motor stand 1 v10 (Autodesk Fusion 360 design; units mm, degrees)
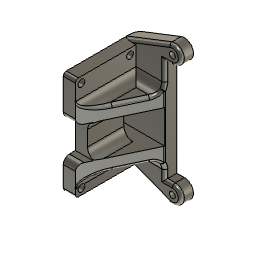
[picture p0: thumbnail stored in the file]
sketch "草图1" plane through (0, 0, 0) normal (1, 0, 0) x axis (0, 1, 0)
  line L1 (-10, -17) -> (10, -17)
  line L2 (10, -7.25) -> (10, 3.75)
  line L3 (10, 3.75) -> (6, 3.75)
  line L4 (-10, 3.75) -> (-6, -7.25)
  line L5 (-10, -7.25) -> (-10, 3.75)
  line L6 (-10, 17) -> (10, -17)
  line L7 (6, 3.75) -> (6, -7.25)
  line L8 (6, -7.25) -> (10, -7.25)
  line L9 (10, 0) -> (-10, 0)
  line L10 (10, -17) -> (10, 17)
  line L11 (-6, -7.25) -> (-10, -7.25)
  line L12 (-10, 17) -> (-10, -17)
  line L13 (10, 17) -> (-10, 17)
  line L14 (-6, 3.75) -> (-10, -7.25)
  line L15 (0, -17) -> (0, 17)
  line L16 (-10, 3.75) -> (-6, 3.75)
  line L17 (-6, 3.75) -> (-6, -7.25)
  line L18 (10, 17) -> (-10, -17)
  line L19 (10, -1.75) -> (-10, -1.75)
  circle C1 centre (-8, 15) radius 1.125
  circle C2 centre (-8, -15) radius 1.125
  circle C3 centre (8, 15) radius 1.125
  circle C4 centre (0, 8) radius 1.3
  circle C5 centre (0, 8) radius 4
  circle C6 centre (0, 8) radius 3
  circle C7 centre (8, -15) radius 1.125
  point P5 (0, 0)
  point P15 (0, 0)
  point P6 (-8, -1.75)
  point P8 (-10, -7.25)
  point P25 (0, 17)
  point P26 (0, -17)
  point P18 (10, -7.25)
  point P11 (6, -7.25)
  point P13 (-6, -7.25)
  point P9 (6, 3.75)
  point P24 (-6, 3.75)
  point P7 (-10, 3.75)
  point P14 (10, 3.75)
  point P4 (10, -1.75)
  point P20 (-10, -1.75)
  point P10 (0, 8)
  point P21 (-10, 0)
  point P29 (10, 0)
  point P16 (10, 17)
  point P17 (-10, 17)
  point P22 (10, -17)
  point P28 (-8, 15)
  horizontal L1
  perpendicular L1 L12
  parallel L1 L13
  parallel L10 L12
  coincident P5 L6
  coincident P5 L18
  coincident P5 P15
  horizontal L11
  perpendicular L11 L17
  parallel L11 L16
  parallel L5 L17
  coincident P6 L14
  coincident P6 L4
  coincident P8 L12
  coincident P6 L19
  midpoint P25 L13
  midpoint P26 L1
  symmetric P8 P18 L15
  symmetric P11 P13 L15
  symmetric P9 P24 L15
  symmetric P7 P14 L15
  midpoint P4 L2
  midpoint P20 L5
  coincident P10 L15
  midpoint P21 L12
  midpoint P29 L10
  symmetric C1 C3 L15
  symmetric C1 C2 L9
  symmetric C3 L9 C7
  concentric C4 C6
  concentric C5 C6
  dimension "d1" distance P16 P17 = 20
  dimension "d2" distance P16 P22 = 34
  dimension "d3" distance P13 P24 = 11
  dimension "d4" distance P7 P24 = 4
  dimension "d5" diameter C4 = 2.6
  dimension "d6" distance P28 L15 = 8
  dimension "d7" distance P28 L9 = 15
  dimension "d8" diameter C1 = 2.25
  dimension "d9" distance P10 P28 = 7
  dimension "d10" diameter C6 = 6
  dimension "d11" diameter C5 = 8
  dimension "d12" distance L1 L8 = 9.75 (= "10.25 mm - 0.5 mm")
extrude "拉伸1" new body sketch "草图1" profile of L1 C1 C2 L3 C3 L7 L8 L10 L11 L12 C7 L13 L16 L17 along normal blind 4
sketch "草图2" plane through (0, 10, 0) normal (0, 1, 0) x axis (-1, 0, 0)
  line L1 (0, 17) -> (0, 3.75)
  line L2 (-4, 17) -> (0, 17)
  line L3 (-4, 3.75) -> (-4, 17)
  line L4 (0, 3.75) -> (-4, 3.75)
  line L5 (0, 17) -> (-4, 17)
  line L6 (0, -17) -> (0, 17)
  line L7 (-4, -17) -> (0, -17)
  line L8 (-4, 17) -> (-4, -17)
  line L9 (-13.5, 17) -> (-4, 17)
  line L10 (-13.5, -17) -> (-13.5, 17)
  line L11 (-4, -17) -> (-13.5, -17)
  line L12 (-4, 17) -> (-4, -17)
  line L13 (0, 0) -> (-13.5, 0)
  line L14 (-14.9132, 22.7962) -> (0, 17)
  line L15 (-14.9132, -22.7962) -> (0, -17)
  line L16 (-16, 17) -> (-13.5, 17)
  line L17 (-16, -17) -> (-13.5, -17)
  line L18 (-2, -17) -> (-2, 17)
  line L19 (10.9132, 22.7962) -> (-4, 17)
  line L20 (9.5, 17) -> (0, 17)
  line L21 (9.5, -17) -> (9.5, 17)
  line L22 (12, 17) -> (9.5, 17)
  line L23 (0, -17) -> (9.5, -17)
  line L24 (12, -17) -> (9.5, -17)
  line L25 (10.9132, -22.7962) -> (-4, -17)
  circle C1 centre (-6, 0) radius 0.975
  circle C2 centre (-16, 20) radius 0.975
  circle C3 centre (-16, -20) radius 0.975
  circle C4 centre (-16, 20) radius 3
  circle C5 centre (-16, -20) radius 3
  circle C6 centre (12, 20) radius 3
  circle C7 centre (12, 20) radius 0.975
  circle C8 centre (12, -20) radius 3
  circle C9 centre (12, -20) radius 0.975
  point P4 (-4, 17)
  point P6 (-4, 17)
  point P13 (-13.5, 0)
  point P1 (0, 0)
  point P14 (0, 0)
  point P3 (0, 17)
  point P19 (0, 17)
  point P20 (-14.9132, 22.7962)
  point P21 (0, -17)
  point P22 (-14.9132, -22.7962)
  point P24 (-16, 17)
  point P25 (-16, -17)
  point P26 (-2, 17)
  point P27 (-2, -17)
  point P30 (0, 17)
  point P10 (-13.5, 17)
  point P31 (9.5, 17)
  point P11 (-13.5, -17)
  point P34 (9.5, -17)
  point P12 (-4, -17)
  point P36 (0, -17)
  point P28 (-4, 17)
  point P29 (10.9132, 22.7962)
  point P40 (-4, -17)
  point P41 (10.9132, -22.7962)
  point P35 (12, 17)
  point P37 (12, -17)
  point P7 (0, 17)
  point P8 (0, -17)
  point P16 (-16, 20)
  point P17 (-16, -20)
  point P15 (-6, 0)
  horizontal L5
  vertical L6
  horizontal L7
  vertical L8
  coincident P4 P6
  horizontal L9
  vertical L10
  horizontal L11
  vertical L12
  collinear L7 L11
  midpoint L10 P13
  coincident P1 P14
  equal C1 C2
  symmetric L13 C2 C3
  concentric C2 C4
  tangent L9 C4
  coincident P3 P19
  coincident C4 P20
  tangent C4 L14
  symmetric L13 C4 C5
  symmetric L13 P19 P21
  symmetric L13 P20 P22
  coincident C4 P24
  tangent C4 L16
  perpendicular L10 L16
  coincident C5 P25
  tangent C5 L17
  midpoint L5 P26
  midpoint L7 P27
  symmetric P6 L18 P30
  symmetric P10 L18 P31
  symmetric P11 L18 P34
  symmetric P12 L18 P36
  symmetric C2 L18 C7
  symmetric C3 L18 C9
  symmetric C4 L18 C6
  symmetric P19 L18 P28
  symmetric P20 L18 P29
  symmetric P21 L18 P40
  symmetric P22 L18 P41
  symmetric C5 L18 C8
  symmetric P24 L18 P35
  symmetric P25 L18 P37
  dimension "d15" distance P7 P8 = 34
  dimension "d16" distance P6 P7 = 4
  dimension "d17" diameter C1 = 1.95
  dimension "d18" distance P16 P17 = 40
  dimension "d19" distance P15 P16 = 10
  dimension "d20" distance L12 P15 = 2
  dimension "d21" distance L10 P16 = 2.5
extrude "拉伸2" add sketch "草图2" profile of L1 L2 L3 L4 L5 L6 L7 L8 L9 L10 L11 L12 C1 C2 C3 C4 L14 L15 C5 L16 L17 L19 L25 along normal blind 4
sketch "草图3" plane through (0, 0, -17) normal (0, 0, -1) x axis (1, 0, 0)
  line L1 (0, -10) -> (0, 10)
  line L2 (4, -10) -> (0, -10)
  line L3 (4, 10) -> (4, -10)
  line L4 (0, 10) -> (4, 10)
  line L5 (13.5, -10) -> (4, 10)
  line L6 (4, -10) -> (13.5, -10)
  point P5 (4, 10)
  point P7 (4, 10)
  point P6 (13.5, -10)
  point P8 (13.5, -10)
  point P4 (4, -10)
  point P9 (4, -10)
  coincident P5 P7
  coincident P6 P8
  coincident P4 P9
extrude "拉伸3" sketch "草图3" profile of L3 L5 L6 blind -4
extrude "拉伸4" sketch "草图3" profile of L3 L5 L6 blind 4
fillet "圆角1" radius 3
fillet "圆角2" radius 1
fillet "圆角3" radius 2
fillet "圆角4" radius 1
fillet "圆角5" radius 1
fillet "圆角6" radius 2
